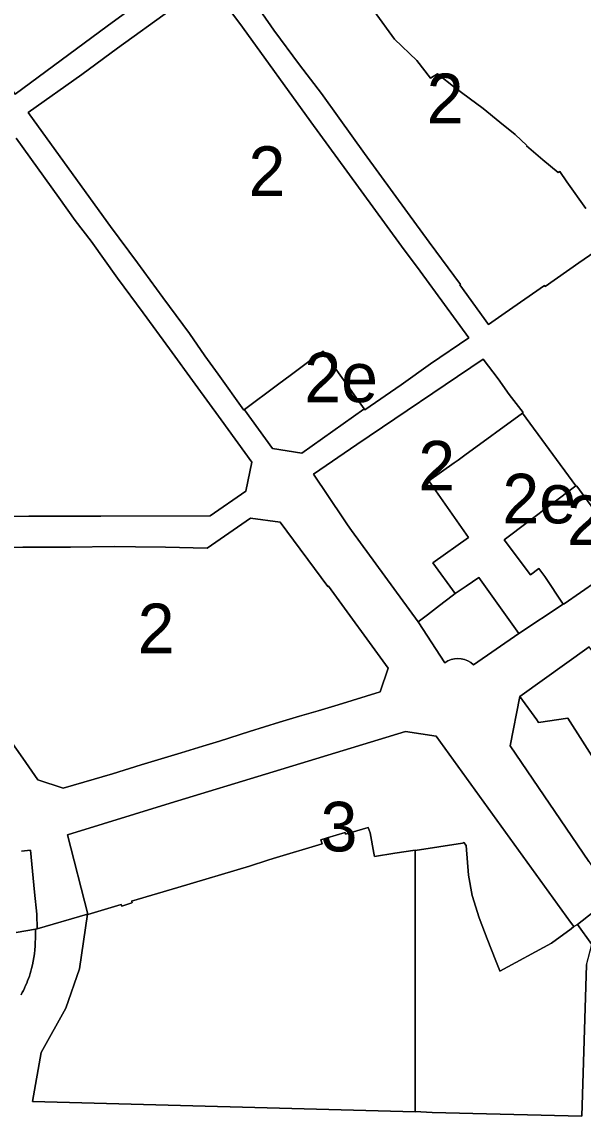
# Model space of a CAD drawing. Extents: x 598968 to 613553, y 4409678 to 4430833.
# Drawn here: x 608272.6 to 608408.5, y 4415521.6 to 4415786.4 of the extents above; entities that cross this region are included whole.
import ezdxf

# ---------------------------------------------------------------- set-up
doc = ezdxf.new("R2010")
doc.units = 0
for name, color, linetype in [('1', 7, 'Continuous'), ('SUBZONA 2e. CARRERS DE CASES. amb projecte especial', 7, 'Continuous'), ('ZONA 2. CARRERS DE CASES. Cases de trast', 7, 'Continuous'), ("ZONA 3. ILLES  D'EDIFICIS ENTRE MITGERES. EIXAMPLE.", 7, 'Continuous'), ('ZONA 3.2. Volumentría específica - ANNEX III B', 7, 'Continuous'), ('ZONA 7. CONJUNTS AMB ORDENACIONS ESPECÍFIQUES', 7, 'Continuous')]:
    doc.layers.add(name, color=color, linetype=linetype)

msp = doc.modelspace()

# ---------------------------------------------------------------- linework, layer by layer
at = {"layer": '1'}
for points in [[(608314.376, 4415800.8157), (608309.5061, 4415797.1749), (608297.9903, 4415788.8408), (608293.2353, 4415785.3996), (608270.9422, 4415768.919), (608251.7373, 4415795.6434), (608228.9125, 4415826.9776), (608253.0021, 4415840.4378), (608276.3818, 4415853.2581), (608290.6517, 4415833.4386), (608308.8426, 4415808.4246)], [(608406.7109, 4415674.1127), (608406.94, 4415674.051), (608419.7052, 4415656.5679), (608403.8649, 4415645.5793), (608403.6097, 4415645.5), (608392.9211, 4415638.3829), (608381.9188, 4415630.8398), (608381.2734, 4415631.3755), (608380.5529, 4415631.8048), (608379.7745, 4415632.1173), (608378.9572, 4415632.3056), (608378.1205, 4415632.3651), (608377.2847, 4415632.2942), (608376.4701, 4415632.0949), (608375.6961, 4415631.7717), (608374.9814, 4415631.3326), (608368.4947, 4415641.1904), (608352.4082, 4415663.3376), (608351.4015, 4415664.6918), (608350.4236, 4415666.1497), (608343.1437, 4415676.927), (608353.6374, 4415684.1668), (608384.2754, 4415704.835), (608387.8779, 4415700.0283), (608390.571, 4415696.2421), (608393.9602, 4415691.8618), (608393.8166, 4415691.7572)], [(608392.9211, 4415638.3829), (608383.2112, 4415651.9425), (608380.1326, 4415649.87), (608377.4501, 4415648.0643), (608376.7837, 4415647.5528), (608373.6677, 4415645.161), (608370.756, 4415642.926), (608368.4947, 4415641.1904), (608374.9814, 4415631.3326), (608375.6961, 4415631.7717), (608376.4701, 4415632.0949), (608377.2847, 4415632.2942), (608378.1205, 4415632.3651), (608378.9572, 4415632.3056), (608379.7745, 4415632.1173), (608380.5529, 4415631.8048), (608381.2734, 4415631.3755), (608381.9188, 4415630.8398)], [(608367.8302, 4415585.857), (608367.8302, 4415585.961), (608362.8929, 4415585.2244), (608357.9136, 4415584.459), (608357.7482, 4415585.2252), (608356.8929, 4415590.1204), (608356.4124, 4415591.4117), (608356.4, 4415591.4451), (608356.3929, 4415591.4642), (608350.953, 4415589.8241), (608350.833, 4415590.2141), (608346.493, 4415588.944), (608344.9431, 4415588.434), (608345.2431, 4415587.464), (608333.3832, 4415583.9539), (608332.0984, 4415583.5384), (608327.7233, 4415582.1238), (608310.3655, 4415576.9035), (608299.1437, 4415573.6234), (608299.1696, 4415573.541), (608299.2537, 4415573.2734), (608299.199, 4415573.2571), (608299.2153, 4415573.2059), (608296.7747, 4415572.4156), (608296.6354, 4415572.8012), (608288.5426, 4415570.3818), (608288.5205, 4415570.4681), (608288.5038, 4415570.4632), (608286.5189, 4415557.2764), (608283.2139, 4415547.6934), (608277.2547, 4415536.9934), (608275.1841, 4415525.1335), (608367.8304, 4415522.6685), (608367.8304, 4415522.7202)], [(608405.5358, 4415566.9639), (608400.7913, 4415563.4339), (608388.2915, 4415556.6838), (608388.2605, 4415556.7696), (608388.2527, 4415556.7652), (608387.3627, 4415559.1751), (608385.2102, 4415564.5075), (608383.2527, 4415569.6049), (608381.6127, 4415575.0248), (608380.6827, 4415579.9448), (608380.1461, 4415587.1097), (608379.6024, 4415587.7816), (608379.2517, 4415587.6284), (608367.8302, 4415585.857), (608367.8304, 4415522.7202), (608371.923, 4415522.4853), (608408.1425, 4415521.596), (608409.3024, 4415558.1956), (608410.5324, 4415563.1655), (608407.0624, 4415567.9754), (608406.2224, 4415567.4554)]]:
    msp.add_lwpolyline(points, close=True, dxfattribs=at)
for points in [[(608322.9415, 4415789.2597), (608325.9815, 4415785.1198), (608342.5213, 4415762.2004), (608351.2813, 4415750.3307), (608364.5012, 4415732.1712), (608369.0011, 4415726.0614), (608380.8011, 4415709.9818), (608371.5412, 4415703.6317), (608364.4109, 4415698.6121), (608355.6014, 4415692.5215), (608355.4357, 4415692.7553), (608355.3814, 4415692.7115), (608340.3716, 4415682.0114), (608333.2717, 4415683.1512), (608326.4718, 4415692.561), (608326.4546, 4415692.5836), (608326.4486, 4415692.5791), (608326.3318, 4415692.491), (608320.0618, 4415701.1908), (608316.8918, 4415705.5707), (608313.1819, 4415710.9805), (608306.7319, 4415719.7403), (608300.5419, 4415728.1401), (608293.9953, 4415736.9139), (608284.9821, 4415749.4295), (608274.0921, 4415764.5291), (608287.062, 4415773.6593), (608295.7418, 4415780.0993), (608308.6817, 4415789.4295)], [(608418.0005, 4415735.3621), (608407.4007, 4415728.102), (608399.3008, 4415722.412), (608399.1408, 4415722.6219), (608389.5893, 4415716.02), (608385.541, 4415713.2218), (608378.611, 4415722.8216), (608378.7385, 4415722.9057), (608371.146, 4415733.1173), (608365.9211, 4415740.2611), (608355.5112, 4415754.5807), (608349.3713, 4415763.1405), (608345.1013, 4415769.0804), (608339.7613, 4415776.0402), (608333.5814, 4415784.43), (608330.8314, 4415788.3399)], [(608357.8311, 4415789.0403), (608362.761, 4415782.2805), (608368.221, 4415777.0607), (608371.481, 4415772.7708), (608373.2109, 4415773.8808), (608377.5009, 4415770.4509), (608384.2608, 4415765.4511), (608388.2808, 4415762.1612), (608392.0208, 4415759.1613), (608394.8307, 4415756.5214), (608394.7273, 4415756.3989), (608398.6707, 4415753.0715), (608402.4207, 4415749.9416), (608402.8153, 4415750.215), (608404.5307, 4415747.7217), (608409.1106, 4415741.2618)], [(608271.1722, 4415758.2692), (608281.5021, 4415743.9595), (608285.4621, 4415738.3897), (608289.3721, 4415733.3498), (608295.692, 4415724.4401), (608301.982, 4415716.0403), (608308.3119, 4415707.3305), (608314.5152, 4415698.7831), (608320.7918, 4415690.1209), (608328.2418, 4415679.8712), (608326.7918, 4415672.8213), (608318.1819, 4415666.8812), (608291.7222, 4415666.8007), (608274.2925, 4415666.7804), (608258.1626, 4415666.6301)], [(608263.8026, 4415659.2503), (608272.8125, 4415659.2604), (608284.3324, 4415659.3107), (608294.8922, 4415659.4208), (608300.1122, 4415659.3909), (608307.3621, 4415659.2911), (608317.432, 4415659.0913), (608327.9218, 4415666.3414), (608335.1217, 4415665.3815), (608346.6217, 4415649.7419), (608346.8018, 4415649.8729), (608361.2315, 4415630.0324), (608359.3016, 4415624.2724), (608349.1817, 4415621.1423), (608344.2918, 4415619.7022), (608339.7718, 4415618.3822), (608334.9819, 4415616.9721), (608327.702, 4415614.672), (608320.4521, 4415612.3819), (608316.3821, 4415611.1418), (608311.1222, 4415609.5417), (608301.4923, 4415606.6116), (608294.4917, 4415604.4167), (608287.6125, 4415602.4314), (608282.6026, 4415600.9313), (608276.4626, 4415602.9612), (608272.7827, 4415608.2311), (608268.7927, 4415613.9809)], [(608409.8611, 4415583.2539), (608390.7884, 4415611.1929), (608393.1412, 4415623.1231), (608409.911, 4415635.1932)], [(608272.485, 4415585.7222), (608274.703, 4415585.9341), (608275.672, 4415575.7841), (608276.1754, 4415570.5116), (608276.3124, 4415566.8851), (608288.5038, 4415570.4632), (608288.5205, 4415570.4681), (608283.5926, 4415589.7115), (608308.5073, 4415597.3069), (608333.422, 4415604.9022), (608365.4215, 4415614.6627), (608372.8515, 4415613.5228), (608405.4202, 4415568.5365), (608406.2006, 4415567.4585), (608405.5358, 4415566.9639), (608406.2224, 4415567.4554), (608407.0624, 4415567.9754), (608410.9188, 4415570.9362)], [(608409.3024, 4415558.1956), (608408.1425, 4415521.596), (608371.923, 4415522.4853), (608367.8304, 4415522.7202), (608367.8304, 4415522.6685), (608275.1841, 4415525.1335), (608277.2547, 4415536.9934), (608283.2139, 4415547.6934), (608286.5189, 4415557.2764), (608288.5038, 4415570.4632), (608276.3124, 4415566.8851), (608275.8592, 4415566.8119), (608275.8738, 4415566.0401), (608275.8503, 4415565.4827), (608275.8503, 4415564.5628), (608275.8303, 4415563.6428), (608275.7803, 4415562.7228), (608275.7103, 4415561.8128), (608275.6103, 4415560.8928), (608275.4803, 4415559.9828), (608275.3203, 4415559.0828), (608275.1403, 4415558.1828), (608274.9303, 4415557.2928), (608274.7703, 4415556.7028), (608274.5903, 4415556.1028), (608274.4003, 4415555.5028), (608274.1903, 4415554.9128), (608273.9703, 4415554.3229), (608273.7403, 4415553.7429), (608273.4903, 4415553.1729), (608273.2303, 4415552.6029), (608272.9603, 4415552.0329), (608272.6703, 4415551.4829), (608272.3703, 4415550.9329)], [(608410.9188, 4415570.9362), (608407.0624, 4415567.9754), (608410.5324, 4415563.1655)]]:
    msp.add_lwpolyline(points, dxfattribs=at)
at = {"layer": 'SUBZONA 2e. CARRERS DE CASES. amb projecte especial'}
for points in [[(608355.4357, 4415692.7553), (608349.6563, 4415700.9069), (608349.6544, 4415700.9096), (608345.4815, 4415706.7612), (608342.729, 4415704.7325), (608337.8816, 4415701.0911), (608334.4354, 4415698.5984), (608326.4546, 4415692.5836), (608326.4718, 4415692.561), (608333.2717, 4415683.1512), (608340.3716, 4415682.0114), (608355.3814, 4415692.7115)], [(608406.7109, 4415674.1127), (608393.8166, 4415691.7572), (608379.8353, 4415681.5695), (608378.1866, 4415680.3682), (608377.2312, 4415679.6721), (608371.1113, 4415675.322), (608380.6812, 4415661.6724), (608372.0842, 4415655.48), (608372.0913, 4415655.4701), (608377.4501, 4415648.0643), (608380.1326, 4415649.87), (608383.2112, 4415651.9425), (608392.9211, 4415638.3829), (608403.6097, 4415645.5), (608399.1543, 4415652.1675), (608397.7601, 4415654.1175), (608397.7489, 4415654.1331), (608395.7448, 4415652.6311), (608395.714, 4415652.6079), (608389.3811, 4415661.0925)]]:
    msp.add_lwpolyline(points, close=True, dxfattribs=at)
at = {"layer": 'ZONA 2. CARRERS DE CASES. Cases de trast'}
for points in [[(608308.8426, 4415808.4246), (608290.6517, 4415833.4386), (608276.3818, 4415853.2581), (608253.0021, 4415840.4378), (608228.9125, 4415826.9776), (608251.7373, 4415795.6434), (608270.9422, 4415768.919), (608293.2353, 4415785.3996), (608297.9903, 4415788.8408), (608293.5318, 4415794.7191), (608292.0218, 4415796.9291), (608294.2918, 4415798.4491), (608294.5318, 4415798.6091), (608296.6718, 4415800.0391), (608297.5417, 4415800.6191), (608299.9517, 4415802.2391), (608302.4617, 4415803.9292), (608303.2517, 4415804.4592), (608305.4116, 4415805.9092)], [(608393.8166, 4415691.7572), (608393.9602, 4415691.8618), (608390.571, 4415696.2421), (608387.8779, 4415700.0283), (608384.2754, 4415704.835), (608353.6374, 4415684.1668), (608343.1437, 4415676.927), (608350.4236, 4415666.1497), (608351.4015, 4415664.6918), (608352.4082, 4415663.3376), (608368.4947, 4415641.1904), (608370.756, 4415642.926), (608373.6677, 4415645.161), (608376.7837, 4415647.5528), (608377.4501, 4415648.0643), (608372.0913, 4415655.4701), (608372.0842, 4415655.48), (608380.6812, 4415661.6724), (608371.1113, 4415675.322), (608377.2312, 4415679.6721), (608378.1866, 4415680.3682), (608379.8353, 4415681.5695)], [(608403.6097, 4415645.5), (608403.8649, 4415645.5793), (608419.7052, 4415656.5679), (608406.94, 4415674.051), (608406.7109, 4415674.1127), (608389.3811, 4415661.0925), (608395.714, 4415652.6079), (608395.7448, 4415652.6311), (608397.7489, 4415654.1331), (608397.7601, 4415654.1175), (608399.1543, 4415652.1675)]]:
    msp.add_lwpolyline(points, close=True, dxfattribs=at)
for points in [[(608308.6817, 4415789.4295), (608295.7418, 4415780.0993), (608287.062, 4415773.6593), (608274.0921, 4415764.5291), (608284.9821, 4415749.4295), (608293.9953, 4415736.9139), (608300.5419, 4415728.1401), (608306.7319, 4415719.7403), (608313.1819, 4415710.9805), (608316.8918, 4415705.5707), (608320.0618, 4415701.1908), (608326.3318, 4415692.491), (608326.4486, 4415692.5791), (608326.4546, 4415692.5836), (608334.4354, 4415698.5984), (608337.8816, 4415701.0911), (608342.729, 4415704.7325), (608345.4815, 4415706.7612), (608349.6544, 4415700.9096), (608349.6563, 4415700.9069), (608355.4357, 4415692.7553), (608355.6014, 4415692.5215), (608364.4109, 4415698.6121), (608371.5412, 4415703.6317), (608380.8011, 4415709.9818), (608369.0011, 4415726.0614), (608364.5012, 4415732.1712), (608351.2813, 4415750.3307), (608342.5213, 4415762.2004), (608325.9815, 4415785.1198), (608322.9415, 4415789.2597)], [(608330.8314, 4415788.3399), (608333.5814, 4415784.43), (608339.7613, 4415776.0402), (608345.1013, 4415769.0804), (608349.3713, 4415763.1405), (608355.5112, 4415754.5807), (608365.9211, 4415740.2611), (608371.146, 4415733.1173), (608378.7385, 4415722.9057), (608378.611, 4415722.8216), (608385.541, 4415713.2218), (608389.5893, 4415716.02), (608399.1408, 4415722.6219), (608399.3008, 4415722.412), (608407.4007, 4415728.102), (608418.0005, 4415735.3621)], [(608409.1106, 4415741.2618), (608404.5307, 4415747.7217), (608402.8153, 4415750.215), (608402.4207, 4415749.9416), (608398.6707, 4415753.0715), (608394.7273, 4415756.3989), (608394.8307, 4415756.5214), (608392.0208, 4415759.1613), (608388.2808, 4415762.1612), (608384.2608, 4415765.4511), (608377.5009, 4415770.4509), (608373.2109, 4415773.8808), (608371.481, 4415772.7708), (608368.221, 4415777.0607), (608362.761, 4415782.2805), (608357.8311, 4415789.0403)], [(608258.1626, 4415666.6301), (608274.2925, 4415666.7804), (608291.7222, 4415666.8007), (608318.1819, 4415666.8812), (608326.7918, 4415672.8213), (608328.2418, 4415679.8712), (608320.7918, 4415690.1209), (608314.5152, 4415698.7831), (608308.3119, 4415707.3305), (608301.982, 4415716.0403), (608295.692, 4415724.4401), (608289.3721, 4415733.3498), (608285.4621, 4415738.3897), (608281.5021, 4415743.9595), (608271.1722, 4415758.2692)], [(608268.7927, 4415613.9809), (608272.7827, 4415608.2311), (608276.4626, 4415602.9612), (608282.6026, 4415600.9313), (608287.6125, 4415602.4314), (608294.4917, 4415604.4167), (608301.4923, 4415606.6116), (608311.1222, 4415609.5417), (608316.3821, 4415611.1418), (608320.4521, 4415612.3819), (608327.702, 4415614.672), (608334.9819, 4415616.9721), (608339.7718, 4415618.3822), (608344.2918, 4415619.7022), (608349.1817, 4415621.1423), (608359.3016, 4415624.2724), (608361.2315, 4415630.0324), (608346.8018, 4415649.8729), (608346.6217, 4415649.7419), (608335.1217, 4415665.3815), (608327.9218, 4415666.3414), (608317.432, 4415659.0913), (608307.3621, 4415659.2911), (608300.1122, 4415659.3909), (608294.8922, 4415659.4208), (608284.3324, 4415659.3107), (608272.8125, 4415659.2604), (608263.8026, 4415659.2503)]]:
    msp.add_lwpolyline(points, dxfattribs=at)
at = {"layer": "ZONA 3. ILLES  D'EDIFICIS ENTRE MITGERES. EIXAMPLE."}
msp.add_lwpolyline([(608405.5358, 4415566.9639), (608406.2006, 4415567.4585), (608405.4202, 4415568.5365), (608372.8515, 4415613.5228), (608365.4215, 4415614.6627), (608333.422, 4415604.9022), (608308.5073, 4415597.3069), (608283.5926, 4415589.7115), (608288.5205, 4415570.4681), (608288.5426, 4415570.3818), (608296.6354, 4415572.8012), (608296.7747, 4415572.4156), (608299.2153, 4415573.2059), (608299.199, 4415573.2571), (608299.2537, 4415573.2734), (608299.1696, 4415573.541), (608299.1437, 4415573.6234), (608310.3655, 4415576.9035), (608327.7233, 4415582.1238), (608332.0984, 4415583.5384), (608333.3832, 4415583.9539), (608345.2431, 4415587.464), (608344.9431, 4415588.434), (608346.493, 4415588.944), (608350.833, 4415590.2141), (608350.953, 4415589.8241), (608356.3929, 4415591.4642), (608356.4, 4415591.4451), (608356.4124, 4415591.4117), (608356.8929, 4415590.1204), (608357.7482, 4415585.2252), (608357.9136, 4415584.459), (608362.8929, 4415585.2244), (608367.8302, 4415585.961), (608367.8302, 4415585.857), (608379.2517, 4415587.6284), (608379.6024, 4415587.7816), (608380.1461, 4415587.1097), (608380.6827, 4415579.9448), (608381.6127, 4415575.0248), (608383.2527, 4415569.6049), (608385.2102, 4415564.5075), (608387.3627, 4415559.1751), (608388.2527, 4415556.7652), (608388.2605, 4415556.7696), (608388.2915, 4415556.6838), (608400.7913, 4415563.4339)], close=True, dxfattribs=at)
msp.add_lwpolyline([(608271.2155, 4415566.0616), (608275.8592, 4415566.8119), (608276.3124, 4415566.8851), (608276.1754, 4415570.5116), (608275.672, 4415575.7841), (608274.703, 4415585.9341), (608272.485, 4415585.7222)], dxfattribs=at)
at = {"layer": 'ZONA 3.2. Volumentría específica - ANNEX III B'}
msp.add_lwpolyline([(608272.3703, 4415550.9329), (608272.6703, 4415551.4829), (608272.9603, 4415552.0329), (608273.2303, 4415552.6029), (608273.4903, 4415553.1729), (608273.7403, 4415553.7429), (608273.9703, 4415554.3229), (608274.1903, 4415554.9128), (608274.4003, 4415555.5028), (608274.5903, 4415556.1028), (608274.7703, 4415556.7028), (608274.9303, 4415557.2928), (608275.1403, 4415558.1828), (608275.3203, 4415559.0828), (608275.4803, 4415559.9828), (608275.6103, 4415560.8928), (608275.7103, 4415561.8128), (608275.7803, 4415562.7228), (608275.8303, 4415563.6428), (608275.8503, 4415564.5628), (608275.8503, 4415565.4827), (608275.8738, 4415566.0401), (608275.8592, 4415566.8119), (608271.2155, 4415566.0616)], dxfattribs=at)
at = {"layer": 'ZONA 7. CONJUNTS AMB ORDENACIONS ESPECÍFIQUES'}
for points in [[(608432.5334, 4415603.6723), (608430.5408, 4415606.4539), (608422.8103, 4415617.2633), (608418.446, 4415623.3635), (608418.1505, 4415623.7733), (608409.911, 4415635.1932), (608393.1412, 4415623.1231), (608397.2142, 4415617.5055), (608397.6888, 4415616.8509), (608404.7162, 4415617.92), (608428.3066, 4415580.9541), (608430.4009, 4415581.9342), (608433.7414, 4415583.5403), (608436.4761, 4415584.855), (608439.6702, 4415586.2231), (608440.7969, 4415586.7057), (608440.9807, 4415586.7844), (608440.9603, 4415586.8244), (608439.3042, 4415590.1703), (608432.5608, 4415603.634)], [(608428.3066, 4415580.9541), (608404.7162, 4415617.92), (608397.6888, 4415616.8509), (608397.2142, 4415617.5055), (608393.1412, 4415623.1231), (608390.7884, 4415611.1929), (608409.8611, 4415583.2539), (608416.5811, 4415573.1941), (608417.7298, 4415573.754), (608418.1714, 4415573.9693), (608422.551, 4415576.1042), (608424.0465, 4415578.0797), (608424.711, 4415579.2142), (608425.0668, 4415579.4278), (608426.9109, 4415580.5342)]]:
    msp.add_lwpolyline(points, close=True, dxfattribs=at)

# ---------------------------------------------------------------- texts
at = {"layer": 'SUBZONA 2e. CARRERS DE CASES. amb projecte especial'}
for p in [(608340.9452, 4415694.3863), (608388.9111, 4415665.0701)]:
    msp.add_text('2e', height=12, dxfattribs=at).set_placement(p)
at = {"layer": 'ZONA 2. CARRERS DE CASES. Cases de trast'}
for p in [(608370.5921, 4415761.9008), (608327.4466, 4415744.3131), (608368.5519, 4415673.0127), (608404.5431, 4415659.8064), (608300.6172, 4415633.6363)]:
    msp.add_text('2', height=12, dxfattribs=at).set_placement(p)
at = {"layer": "ZONA 3. ILLES  D'EDIFICIS ENTRE MITGERES. EIXAMPLE."}
msp.add_text('3', height=12, dxfattribs=at).set_placement((608344.8966, 4415585.6732))

doc.saveas('drawing.dxf')
